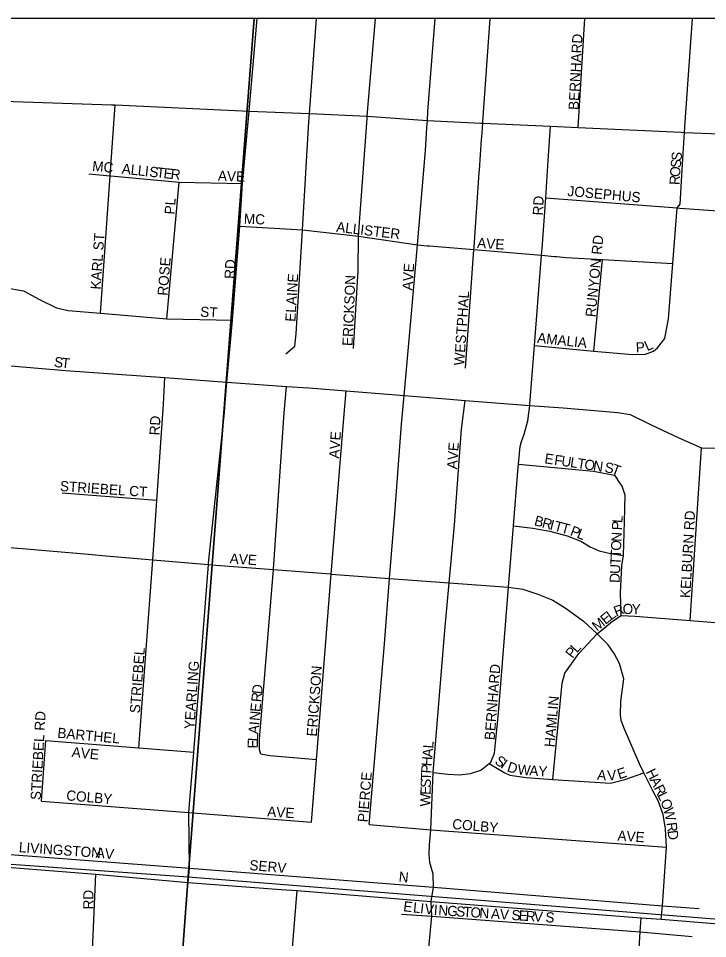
# Model space of a CAD drawing. Extents: x 0 to 34, y 0 to 22.
# Drawn here: x 6.235 to 6.877, y 20.042 to 20.9 of the extents above; entities that cross this region are included whole.
import ezdxf

# ---------------------------------------------------------------- set-up
doc = ezdxf.new("R2010")
doc.units = 0
for name, color, linetype in [('GM_X_City_Street', 7, 'Continuous'), ('GM_X_City_Street_Text', 7, 'Continuous'), ('GM_X_Section', 7, 'Continuous'), ('GM_X_Township', 7, 'Continuous'), ('GM_X_US_Route', 7, 'Continuous')]:
    doc.layers.add(name, color=color, linetype=linetype)

msp = doc.modelspace()

# ---------------------------------------------------------------- linework, layer by layer
at = {"layer": 'GM_X_City_Street'}
for points in [[(6.42682, 20.53277), (6.42728, 20.53717), (6.42912, 20.56102), (6.43442, 20.61862), (6.44117, 20.70645), (6.44366, 20.74602), (6.44983, 20.81341), (6.45721, 20.9)], [(6.50562, 20.80374), (6.50608, 20.81127), (6.5127, 20.9)], [(6.55979, 20.80674), (6.55995, 20.8089), (6.56762, 20.9)], [(6.61562, 20.79792), (6.61563, 20.79796), (6.61605, 20.80495), (6.61655, 20.81312), (6.62347, 20.9)], [(6.66666, 20.78725), (6.6668, 20.78931), (6.66772, 20.80239), (6.66781, 20.80367), (6.67468, 20.9)], [(6.75673, 20.79832), (6.76303, 20.9)], [(6.85604, 20.79875), (6.85606, 20.79899), (6.86321, 20.9)], [(6.31132, 20.6251), (6.31903, 20.73553), (6.32028, 20.75324), (6.32492, 20.81934)], [(6.48416, 20.58724), (6.49233, 20.5946), (6.49379, 20.60595), (6.49943, 20.70306), (6.50562, 20.80374)], [(6.54722, 20.59225), (6.55161, 20.66503), (6.55188, 20.69713), (6.55979, 20.80674)], [(6.5918, 20.52186), (6.59428, 20.54845), (6.60171, 20.62827), (6.60687, 20.68887), (6.61435, 20.77674), (6.61562, 20.79792)], [(6.7288, 20.76754), (6.731, 20.7995)], [(6.85362, 20.75885), (6.85363, 20.75898), (6.85574, 20.7938), (6.85604, 20.79875)], [(6.66448, 20.75642), (6.66463, 20.75854), (6.66666, 20.78725)], [(6.70637, 20.51248), (6.70976, 20.52491), (6.71158, 20.53928), (6.71173, 20.54042), (6.71602, 20.59497), (6.72264, 20.67919), (6.72314, 20.68551), (6.72641, 20.73289), (6.7288, 20.76754), (6.7288, 20.76754)], [(6.83074, 20.5928), (6.83745, 20.60172), (6.841, 20.61984), (6.84495, 20.67139), (6.84902, 20.72339), (6.85169, 20.72698), (6.85362, 20.75885)], [(6.30027, 20.75506), (6.32028, 20.75324), (6.32072, 20.7532)], [(6.32072, 20.7532), (6.38458, 20.7474), (6.44366, 20.74602)], [(6.65942, 20.68448), (6.65958, 20.68674), (6.66448, 20.75642)], [(6.3729, 20.6199), (6.38458, 20.7474)], [(6.72641, 20.73289), (6.84902, 20.72339), (6.85159, 20.72319), (6.94923, 20.7163)], [(6.44117, 20.70645), (6.49943, 20.70306), (6.55188, 20.69713), (6.60687, 20.68887), (6.61579, 20.68812), (6.6181, 20.68793)], [(6.6181, 20.68793), (6.65942, 20.68448), (6.72264, 20.67919), (6.73474, 20.67818), (6.73637, 20.67805)], [(6.65168, 20.57405), (6.65942, 20.68448)], [(6.73637, 20.67805), (6.74564, 20.67727), (6.77933, 20.67527), (6.84495, 20.67139)], [(6.77146, 20.58992), (6.77933, 20.67527)], [(6.14243, 20.59481), (6.15933, 20.61333), (6.17772, 20.63292), (6.19317, 20.64311), (6.21, 20.64832), (6.22177, 20.64911), (6.23949, 20.64595), (6.25442, 20.63792), (6.27011, 20.63026), (6.28103, 20.62766), (6.31132, 20.6251), (6.3729, 20.6199), (6.43442, 20.61862)], [(6.71602, 20.59497), (6.77146, 20.58992), (6.80745, 20.58664), (6.81958, 20.58705), (6.82687, 20.58987), (6.83074, 20.5928)], [(6.17619, 20.58057), (6.27866, 20.57192), (6.37132, 20.56521), (6.42912, 20.56102), (6.4848, 20.557), (6.5056, 20.55549), (6.54038, 20.55273), (6.59428, 20.54845), (6.63341, 20.54535), (6.6512, 20.54397), (6.71158, 20.53928), (6.74271, 20.53687), (6.79375, 20.53274), (6.80507, 20.53089), (6.82488, 20.52121), (6.85068, 20.50907), (6.87164, 20.49973), (6.90498, 20.49953), (6.92871, 20.50006)], [(6.36985, 20.54043), (6.37132, 20.56521)], [(6.48256, 20.53223), (6.4848, 20.557)], [(6.53813, 20.52721), (6.54038, 20.55273)], [(6.64776, 20.51721), (6.6512, 20.54397)], [(6.34692, 20.22), (6.35994, 20.39533), (6.36372, 20.45065), (6.36985, 20.54043)], [(6.39285, 20.09457), (6.39407, 20.10799), (6.3937, 20.15963), (6.39813, 20.21591), (6.4119, 20.39091), (6.412, 20.3921), (6.42682, 20.53277)], [(6.51256, 20.2089), (6.46912, 20.21253), (6.46083, 20.21429), (6.45943, 20.21813), (6.45933, 20.228), (6.47261, 20.38622), (6.47265, 20.38672), (6.48256, 20.53223)], [(6.50788, 20.15065), (6.51256, 20.2089), (6.52647, 20.38208), (6.53813, 20.52721)], [(6.56165, 20.14871), (6.576, 20.3169), (6.58082, 20.37802), (6.58559, 20.43851), (6.5918, 20.52186)], [(6.61958, 20.07678), (6.62166, 20.09018), (6.62136, 20.1024), (6.61838, 20.11312), (6.61779, 20.12057), (6.61809, 20.12951), (6.61928, 20.14351), (6.62136, 20.19704), (6.63246, 20.32932), (6.63649, 20.37386), (6.64138, 20.42779), (6.64776, 20.51721)], [(6.62136, 20.19704), (6.63502, 20.19558), (6.64599, 20.19489), (6.65626, 20.1961), (6.66583, 20.19925), (6.67377, 20.20549), (6.67514, 20.20657), (6.67879, 20.2152), (6.68253, 20.25231), (6.69184, 20.36968), (6.69639, 20.42695), (6.70044, 20.4781), (6.70106, 20.48456), (6.70262, 20.50082), (6.7039, 20.50572), (6.70637, 20.51248)], [(6.86125, 20.33878), (6.87164, 20.49973)], [(6.70106, 20.48456), (6.77094, 20.47796), (6.79055, 20.47435), (6.79346, 20.4701)], [(6.79695, 20.34354), (6.79608, 20.36446), (6.79757, 20.38986), (6.79898, 20.39931), (6.79991, 20.43118), (6.80061, 20.45546), (6.79782, 20.4639), (6.79346, 20.4701)], [(6.36372, 20.45065), (6.27533, 20.45735)], [(5.90511, 20.43387), (5.93992, 20.43104), (6.00038, 20.42612), (6.03556, 20.42327), (6.10822, 20.41695), (6.15314, 20.41304), (6.22278, 20.40705), (6.24925, 20.40479), (6.25236, 20.40452)], [(6.69639, 20.42695), (6.71444, 20.42492), (6.73028, 20.42218), (6.74645, 20.41754), (6.75919, 20.41261), (6.76776, 20.40743), (6.77637, 20.40376), (6.78691, 20.40118), (6.79898, 20.39931)], [(6.25236, 20.40452), (6.29984, 20.40044), (6.31001, 20.39958), (6.31282, 20.39934)], [(6.31282, 20.39934), (6.35994, 20.39533), (6.4119, 20.39091), (6.41478, 20.39067), (6.47261, 20.38622), (6.52559, 20.38215), (6.52647, 20.38208), (6.58082, 20.37802), (6.63649, 20.37386), (6.69184, 20.36968), (6.70521, 20.36785), (6.7191, 20.36327), (6.73296, 20.35756), (6.74562, 20.34997), (6.76158, 20.33812), (6.7745, 20.32636)], [(6.7745, 20.32636), (6.78887, 20.33809), (6.79695, 20.34354), (6.80985, 20.3428), (6.86125, 20.33878), (6.91556, 20.33454)], [(6.73306, 20.19064), (6.74171, 20.28022), (6.74426, 20.28964), (6.75729, 20.30786), (6.7745, 20.32636)], [(6.83409, 20.06038), (6.83524, 20.07281), (6.83923, 20.1274), (6.83821, 20.14452), (6.83595, 20.15788), (6.83139, 20.17054), (6.82599, 20.18057), (6.81805, 20.19666), (6.81382, 20.20523), (6.79997, 20.23752), (6.7968, 20.24559), (6.7962, 20.25092), (6.79656, 20.26344), (6.79943, 20.28425), (6.79531, 20.29879), (6.79027, 20.30805), (6.78482, 20.31618), (6.7745, 20.32636)], [(6.25603, 20.17045), (6.26031, 20.22691)], [(6.26031, 20.22691), (6.34692, 20.22), (6.39813, 20.21591)], [(6.67377, 20.20549), (6.68775, 20.19709), (6.69298, 20.19467), (6.70808, 20.19233), (6.73306, 20.19064), (6.78676, 20.18702), (6.80012, 20.19043), (6.81805, 20.19666)], [(6.25603, 20.17045), (6.3937, 20.15963), (6.50788, 20.15065)], [(6.56165, 20.14871), (6.61928, 20.14351), (6.83923, 20.1274)], [(5.88898, 20.13374), (6.0182, 20.12601), (6.12873, 20.11707), (6.18862, 20.1117), (6.3069, 20.10217), (6.39285, 20.09457), (6.47955, 20.0881), (6.49452, 20.08705), (6.61958, 20.07678), (6.81532, 20.06158), (6.83409, 20.06038), (6.90291, 20.05472)], [(6.22275, 20.12091), (6.39407, 20.10799), (6.62166, 20.09018), (6.83524, 20.07281), (6.86941, 20.07033)], [(6.30274, 20.01341), (6.30295, 20.01723), (6.3069, 20.10217)], [(6.44983, 19.56648), (6.45764, 19.65267), (6.46691, 19.7663), (6.4691, 19.79318), (6.46968, 19.81066), (6.4734, 19.84711), (6.48078, 19.91923), (6.49452, 20.08705)], [(6.58528, 19.62692), (6.58855, 19.68086), (6.59802, 19.81341), (6.60022, 19.83685), (6.60839, 19.9239), (6.61511, 20.01063), (6.62017, 20.06307), (6.61958, 20.07678)], [(6.59187, 20.06486), (6.62017, 20.06307), (6.81442, 20.04847), (6.86299, 20.0443)], [(6.81231, 19.82851), (6.8152, 19.88321), (6.82217, 19.93943), (6.82604, 19.98114), (6.82426, 19.99157), (6.8186, 20.00974), (6.81383, 20.02464), (6.81353, 20.03298), (6.81442, 20.04847), (6.81532, 20.06158)]]:
    msp.add_lwpolyline(points, dxfattribs=at)
at = {"layer": 'GM_X_Section'}
for p, q in [((6.4544, 20.9), (5.95003, 20.9)), ((6.96615, 20.9), (6.4544, 20.9))]:
    msp.add_line(p, q, dxfattribs=at)
for points in [[(5.95003, 20.9), (5.8928, 20.13549), (6.39308, 20.09979), (6.4544, 20.9)], [(6.4544, 20.9), (6.39308, 20.09979), (6.89954, 20.05948), (6.96615, 20.9)]]:
    msp.add_lwpolyline(points, dxfattribs=at)
for points in [[(5.8928, 20.13549), (6.39308, 20.09979), (6.31814, 19.09172), (5.81902, 19.1295)], [(6.39308, 20.09979), (6.89954, 20.05948), (6.82179, 19.05189), (6.31814, 19.09172)]]:
    msp.add_lwpolyline(points, close=True, dxfattribs=at)
at = {"layer": 'GM_X_Township'}
msp.add_lwpolyline([(9.4, 17.82945), (9.4, 20.9), (4.42993, 20.9)], dxfattribs=at)
at = {"layer": 'GM_X_US_Route'}
msp.add_lwpolyline([(5.49118, 20.85512), (5.52807, 20.85345), (5.65258, 20.84779), (5.68974, 20.8454), (5.69384, 20.84521), (5.88349, 20.83613), (6.03241, 20.82919), (6.03369, 20.82914), (6.12003, 20.82625), (6.32153, 20.81951), (6.32492, 20.81934), (6.44983, 20.81341), (6.50608, 20.81127), (6.55995, 20.8089), (6.61605, 20.80495), (6.66585, 20.80248), (6.66772, 20.80239), (6.731, 20.7995), (6.75673, 20.79832), (6.8528, 20.79392), (6.85574, 20.7938), (6.95519, 20.7898)], dxfattribs=at)

# ---------------------------------------------------------------- texts
at = {"layer": 'GM_X_City_Street_Text'}
for s, height, rotation, p in [('BERNHARD', 0.00947, 86.98599, (6.75707, 20.81449)), ('S', 0.00947, 83.97955, (6.85289, 20.76682)), ('MC', 0.00947, 354.80826, (6.30315, 20.75784)), ('S', 0.00947, 84.33561, (6.85223, 20.7602)), ('A', 0.00947, 353.89148, (6.33067, 20.75533)), ('L', 0.00947, 353.8932, (6.33896, 20.75444)), ('L', 0.00947, 353.8932, (6.34559, 20.75374)), ('I', 0.00947, 353.91475, (6.35222, 20.75303)), ('S', 0.00947, 353.89517, (6.35636, 20.75258)), ('T', 0.00947, 353.8932, (6.36299, 20.75188)), ('E', 0.00947, 353.8932, (6.36962, 20.75117)), ('R', 0.00947, 353.96715, (6.37626, 20.75046)), ('AVE', 0.00947, 357.95571, (6.42055, 20.74867)), ('O', 0.00947, 85.9315, (6.85165, 20.75196)), ('R', 0.00947, 86.57363, (6.8512, 20.7445)), ('JOSEPHUS', 0.00947, 354.88235, (6.74647, 20.73451)), ('PL', 0.00947, 86.42535, (6.38037, 20.71701)), ('RD', 0.00947, 86.98901, (6.72374, 20.71615)), ('MC', 0.00947, 357.39879, (6.44473, 20.70868)), ('ALLISTER', 0.00947, 353.2468, (6.53068, 20.70117)), ('KARL ST', 0.00947, 85.98414, (6.3112, 20.64702)), ('AVE', 0.00947, 356.05688, (6.66227, 20.68617)), ('RUNYON RD', 0.00947, 84.42825, (6.77287, 20.62123)), ('ROSE', 0.00947, 85.23283, (6.37371, 20.64121)), ('RD', 0.00947, 86.98841, (6.43621, 20.65699)), ('AVE', 0.00947, 86.05688, (6.60204, 20.64619)), ('ELAINE', 0.00947, 86.56819, (6.49291, 20.617)), ('ERICKSON', 0.00947, 87.51181, (6.5462, 20.59447)), ('WESTPHAL', 0.00947, 86.13357, (6.65037, 20.57618)), ('ST', 0.00947, 356.42537, (6.40393, 20.62201)), ('AMALIA', 0.00947, 353.88395, (6.71816, 20.59771)), ('P', 0.00947, 1.80356, (6.81056, 20.58856)), ('L', 0.00947, 24.49911, (6.82112, 20.58968)), ('S', 0.00947, 352.16348, (6.26741, 20.57533)), ('T', 0.00947, 354.14844, (6.27438, 20.57438)), ('RD', 0.00947, 86.98901, (6.36621, 20.51115)), ('AVE', 0.00947, 86.05688, (6.5337, 20.48952)), ('AVE', 0.00947, 86.05688, (6.6437, 20.47952)), ('E', 0.00947, 351.55301, (6.72487, 20.48533)), ('F', 0.00947, 351.55116, (6.73395, 20.48399)), ('U', 0.00947, 351.53299, (6.74054, 20.48301)), ('L', 0.00947, 351.55116, (6.74879, 20.48178)), ('T', 0.00947, 351.55116, (6.75538, 20.4808)), ('O', 0.00947, 351.53299, (6.76197, 20.47982)), ('N', 0.00947, 351.55683, (6.77022, 20.47859)), ('S', 0.00947, 351.55116, (6.78094, 20.477)), ('T', 0.00947, 339.37042, (6.78702, 20.47616)), ('STRIEBEL CT', 0.0094697, 356.00885, (6.27311, 20.45951)), ('KELBURN RD', 0.00947, 86.7474, (6.8612, 20.3595)), ('B', 0.00947, 344.93873, (6.71506, 20.42768)), ('R', 0.00947, 344.96391, (6.72231, 20.42573)), ('I', 0.00947, 344.92502, (6.72955, 20.42378)), ('L', 0.00947, 85.46092, (6.79783, 20.42934)), ('T', 0.00947, 344.94234, (6.73357, 20.4227)), ('T', 0.00947, 344.96631, (6.74002, 20.42097)), ('P', 0.00947, 339.33522, (6.74857, 20.41847)), ('L', 0.00947, 338.19352, (6.75477, 20.41614)), ('P', 0.00947, 87.2399, (6.79751, 20.42276)), ('N', 0.00947, 87.50759, (6.79704, 20.41194)), ('O', 0.00947, 87.51581, (6.79667, 20.40362)), ('AVE', 0.00947, 356.04938, (6.43144, 20.39201)), ('T', 0.00947, 87.51566, (6.79609, 20.3903)), ('T', 0.00947, 87.48551, (6.79638, 20.39696)), ('U', 0.00947, 87.48576, (6.79573, 20.38197)), ('D', 0.00947, 87.50759, (6.79536, 20.37364)), ('E', 0.00947, 38.8646, (6.78213, 20.33455)), ('L', 0.00947, 35.88072, (6.78722, 20.33865)), ('R', 0.00947, 21.58496, (6.79208, 20.34226)), ('O', 0.00947, 359.5628, (6.79811, 20.34484)), ('Y', 0.00947, 358.38215, (6.80639, 20.34478)), ('M', 0.00947, 38.87031, (6.77435, 20.32827)), ('STRIEBEL', 0.00947, 85.6036, (6.34787, 20.25203)), ('P', 0.00947, 52.90609, (6.75152, 20.30285)), ('L', 0.00947, 47.35699, (6.75538, 20.30799)), ('YEARLING', 0.00947, 85.97388, (6.39871, 20.23702)), ('ERICKSON', 0.00947, 85.8545, (6.51287, 20.23036)), ('BERNHARD', 0.00947, 85.54362, (6.67874, 20.22698)), ('D', 0.00947, 84.6537, (6.46184, 20.26982)), ('R', 0.00947, 84.62528, (6.46114, 20.26235)), ('E', 0.00947, 84.63737, (6.46029, 20.25323)), ('HAMLIN', 0.00947, 84.90059, (6.73458, 20.22038)), ('STRIEBEL RD', 0.0094697, 86.74973, (6.25537, 20.17116)), ('N', 0.00947, 84.6537, (6.45951, 20.24493)), ('I', 0.00947, 84.61561, (6.45912, 20.24078)), ('BARTHEL', 0.00947, 354.64365, (6.27065, 20.2295)), ('A', 0.00947, 84.74618, (6.45836, 20.23249)), ('E', 0.00947, 89.39891, (6.4579, 20.21937)), ('L', 0.00947, 86.60946, (6.45797, 20.22591)), ('AVE', 0.00947, 354.09695, (6.28399, 20.21163)), ('A', 0.00947, 85.25087, (6.6207, 20.21091)), ('L', 0.00947, 85.24089, (6.62139, 20.21921)), ('H', 0.00947, 85.27446, (6.62001, 20.20261)), ('S', 0.00947, 325.56745, (6.67817, 20.20585)), ('I', 0.00947, 325.57132, (6.68367, 20.20208)), ('P', 0.00947, 86.14411, (6.61957, 20.19599)), ('D', 0.00947, 341.43621, (6.68966, 20.19845)), ('W', 0.00947, 355.00447, (6.69995, 20.1953)), ('A', 0.00947, 355.83823, (6.71089, 20.19435)), ('Y', 0.00947, 356.06317, (6.71925, 20.19374)), ('E', 0.00947, 18.35468, (6.79494, 20.19065)), ('H', 0.00947, 296.37938, (6.81957, 20.1977)), ('PIERCE', 0.00947, 85.23447, (6.56037, 20.15038)), ('T', 0.00947, 88.05989, (6.61935, 20.18941)), ('A', 0.00947, 354.61561, (6.77411, 20.19032)), ('V', 0.00947, 4.30434, (6.78415, 20.18953)), ('E', 0.00947, 88.46955, (6.61899, 20.17611)), ('S', 0.00947, 88.46955, (6.61917, 20.18277)), ('A', 0.00947, 296.3598, (6.82328, 20.19023)), ('R', 0.00947, 296.39609, (6.82698, 20.18276)), ('COLBY', 0.00947, 355.13824, (6.27896, 20.17117)), ('W', 0.00947, 88.47, (6.6187, 20.16527)), ('L', 0.00947, 295.78291, (6.8303, 20.17607)), ('O', 0.00947, 291.76083, (6.83313, 20.17022)), ('AVE', 0.00947, 356.05688, (6.46644, 20.15617)), ('W', 0.00947, 283.87312, (6.83611, 20.16281)), ('COLBY', 0.00947, 355.13323, (6.63897, 20.1445)), ('R', 0.00947, 277.15816, (6.83906, 20.15012)), ('AVE', 0.00947, 356.0574, (6.7931, 20.13367)), ('D', 0.00947, 277.12231, (6.83999, 20.14268)), ('LIVINGSTON', 0.00947, 355.91401, (6.23478, 20.12284)), ('AV', 0.00947, 354.29265, (6.30649, 20.11783)), ('SERV', 0.00947, 355.23887, (6.4498, 20.10617)), ('N', 0.00947, 354.29157, (6.58899, 20.09533)), ('RD', 0.00947, 90, (6.30454, 20.0694)), ('E', 0.00947, 353.12576, (6.5932, 20.06783)), ('L', 0.00947, 353.12738, (6.60231, 20.06673)), ('I', 0.00947, 353.12225, (6.60893, 20.06593)), ('V', 0.00947, 353.76255, (6.61318, 20.06542)), ('I', 0.00947, 355.60667, (6.62179, 20.06448)), ('N', 0.00947, 356.17567, (6.62605, 20.06416)), ('G', 0.00947, 356.24318, (6.63437, 20.0636)), ('S', 0.00947, 356.22772, (6.64269, 20.06306)), ('T', 0.00947, 356.26581, (6.64935, 20.06262)), ('O', 0.00947, 356.23826, (6.656, 20.06218)), ('N', 0.00947, 356.23826, (6.66432, 20.06164)), ('A', 0.00947, 356.25482, (6.67513, 20.06092)), ('V', 0.00947, 356.26007, (6.68345, 20.06038)), ('S', 0.00947, 356.24105, (6.69426, 20.05967)), ('E', 0.00947, 356.26581, (6.70092, 20.05923)), ('R', 0.00947, 356.23278, (6.70757, 20.05879)), ('V', 0.00947, 356.23826, (6.71506, 20.0583)), ('S', 0.00947, 356.22772, (6.72588, 20.05759))]:
    msp.add_text(s, height=height, rotation=rotation, dxfattribs=at).set_placement(p)

doc.saveas('drawing.dxf')
